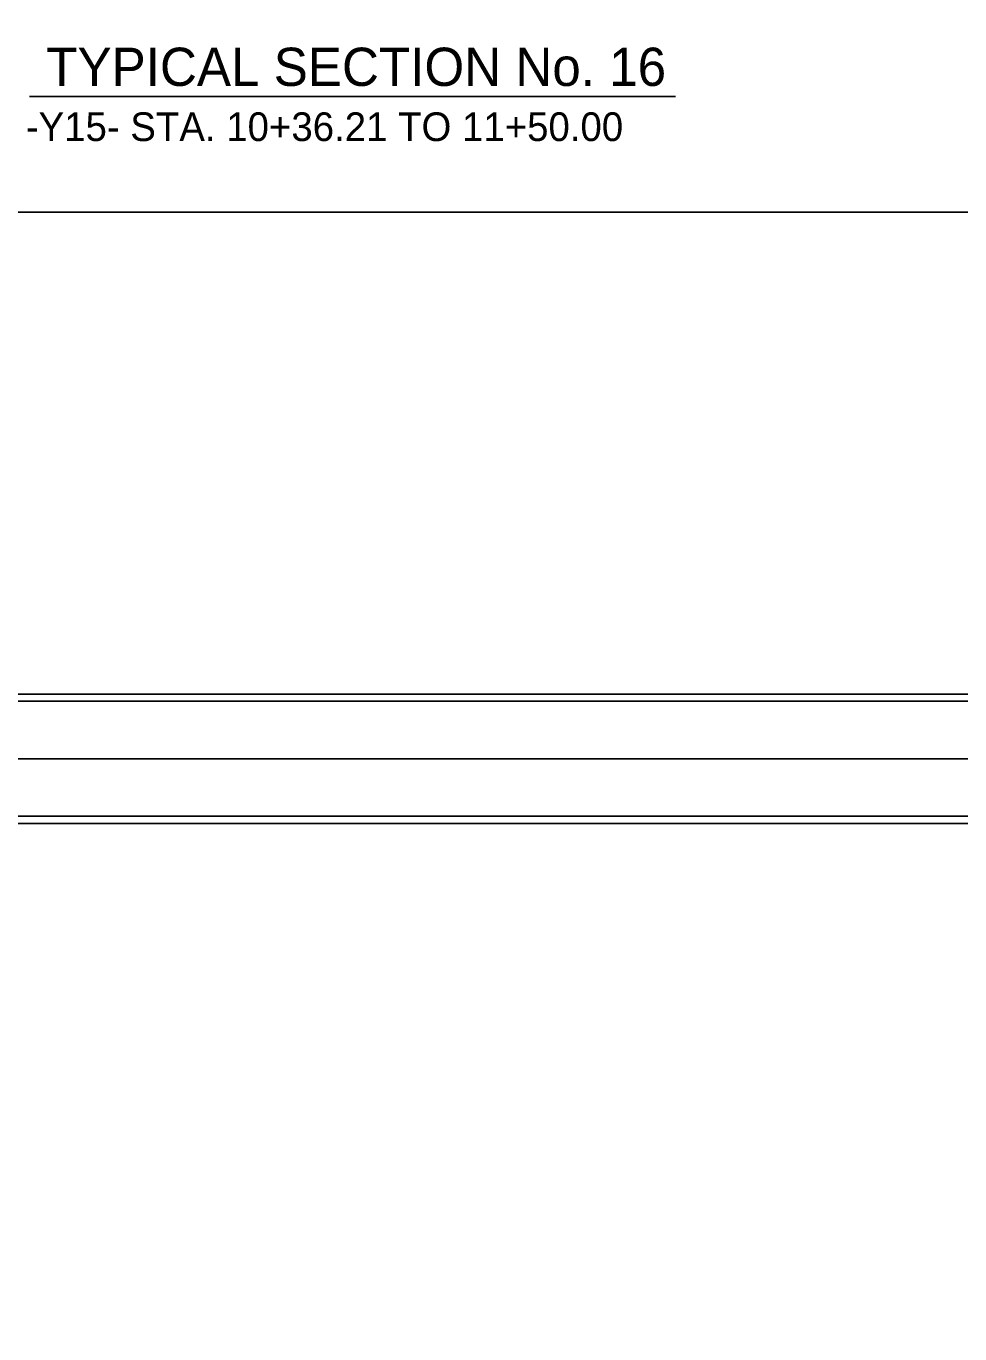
# Model space of a CAD drawing. Extents: x 2320980 to 2456309, y 595047 to 606177.
# Drawn here: x 2455913.1 to 2455978, y 595825.6 to 595916.5 of the extents above; entities that cross this region are included whole.
import ezdxf

# ---------------------------------------------------------------- set-up
doc = ezdxf.new("R2010")
doc.units = 0
for name, color, linetype in [('Old_Level_2', 7, 'Continuous'), ('Old_Level_3', 7, 'Continuous'), ('Sheet Cutting Line CELL', 7, 'Continuous'), ('Sheet Plan CELL', 7, 'Continuous'), ('Sheet Plot Border Inside CELL', 7, 'Continuous'), ('Sheet Plot Border Outside CELL', 7, 'Continuous')]:
    doc.layers.add(name, color=color, linetype=linetype)

msp = doc.modelspace()

# ---------------------------------------------------------------- linework, layer by layer
at = {"layer": 'Old_Level_3'}
msp.add_line((2455913.317, 595911.626), (2455958.238, 595911.626), dxfattribs=at)
at = {"layer": 'Sheet Cutting Line CELL'}
msp.add_line((2456045.507, 595903.574), (2455708.807, 595903.574), dxfattribs=at)
at = {"layer": 'Sheet Plan CELL'}
for points in [[(2455742.104, 595870.076), (2455742.099, 596080.071), (2456002.097, 596080.079), (2456002.099, 596050.066), (2456042.107, 596050.064), (2456042.107, 595870.076)], [(2456042.112, 596080.076), (2455742.104, 596080.076), (2455742.104, 595870.076), (2456042.107, 595870.076)], [(2455742.104, 595651.076), (2455742.099, 595861.071), (2456002.097, 595861.079), (2456002.099, 595831.066), (2456042.107, 595831.064), (2456042.107, 595651.076)], [(2456042.112, 595861.076), (2455742.104, 595861.076), (2455742.104, 595651.076), (2456042.107, 595651.076)]]:
    msp.add_lwpolyline(points, close=True, dxfattribs=at)
at = {"layer": 'Sheet Plot Border Inside CELL'}
for points in [[(2455711.407, 595869.574), (2456044.604, 595869.576), (2456044.607, 596080.574), (2455711.407, 596080.574)], [(2455711.407, 595650.574), (2456044.604, 595650.576), (2456044.607, 595861.574), (2455711.407, 595861.574)]]:
    msp.add_lwpolyline(points, close=True, dxfattribs=at)
at = {"layer": 'Sheet Plot Border Outside CELL'}
for points in [[(2455708.807, 595865.574), (2456045.507, 595865.574), (2456045.507, 596084.574), (2455708.807, 596084.574)], [(2455708.807, 595646.574), (2456045.507, 595646.574), (2456045.507, 595865.574), (2455708.807, 595865.574)]]:
    msp.add_lwpolyline(points, close=True, dxfattribs=at)

# ---------------------------------------------------------------- texts
at = {"layer": 'Old_Level_2'}
for s, height, p in [('TYPICAL SECTION No. 16', 2.66, (2455914.49, 595912.359)), ('-Y15- STA. 10+36.21 TO 11+50.00', 1.995, (2455913.07, 595908.527))]:
    msp.add_text(s, height=height, dxfattribs=at).set_placement(p)

doc.saveas('drawing.dxf')
